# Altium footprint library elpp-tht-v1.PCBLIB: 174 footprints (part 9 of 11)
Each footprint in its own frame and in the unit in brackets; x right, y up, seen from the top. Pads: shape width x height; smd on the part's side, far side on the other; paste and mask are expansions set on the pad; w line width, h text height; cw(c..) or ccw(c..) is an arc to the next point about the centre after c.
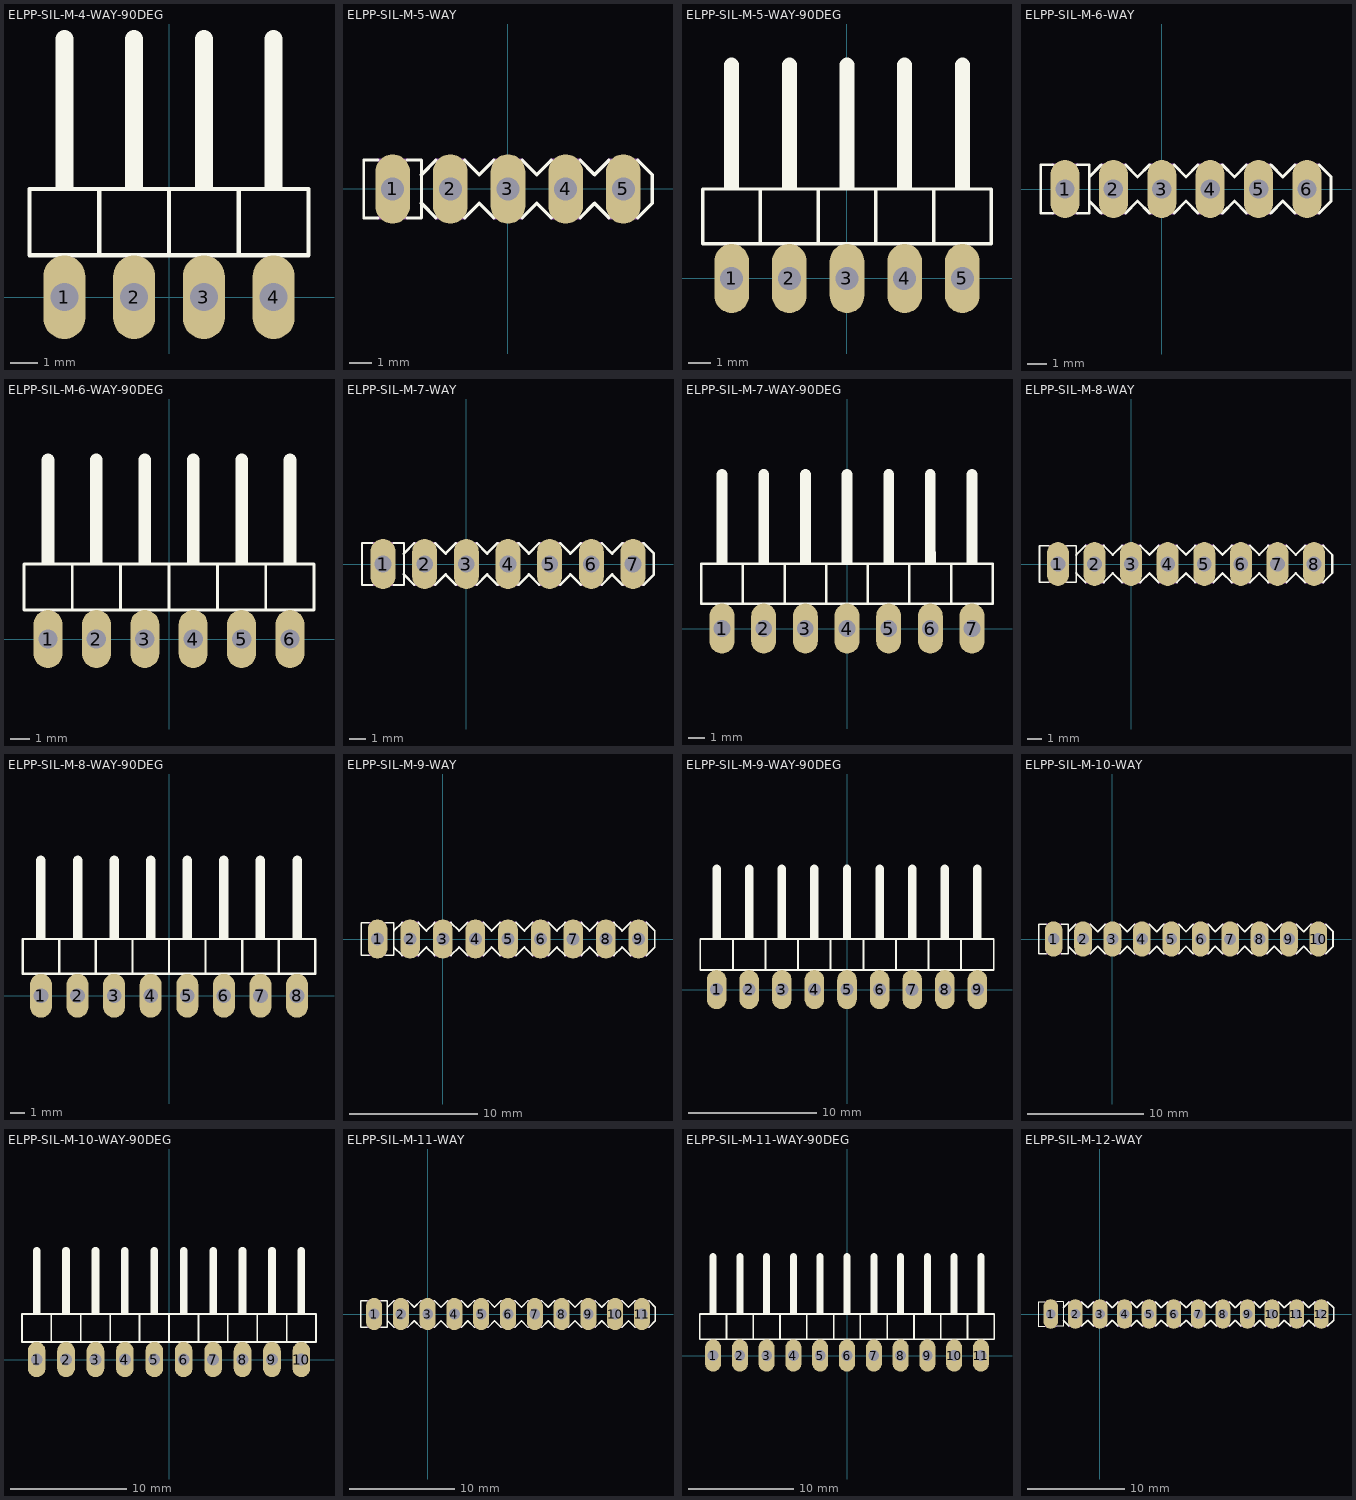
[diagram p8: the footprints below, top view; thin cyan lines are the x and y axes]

## ELPP-SIL-M-4-WAY-90DEG [mil]
pads (4):
  oval 60x120 hole 40: 1(-150,0) 2(-50,0) 3(50,0) 4(150,0)
Top Overlay:
  rectangle: -163,155 -137,185
  rectangle: -63,155 -37,185
  rectangle: 37,155 63,185
  rectangle: 137,155 163,185
  lines w6: -100,60 -100,155 ; -100,60 -200,60 -200,155 -100,155 ; -100,60 0,60 ; -100,155 0,155 ; 0,60 100,60 ; 0,60 0,155 ; 0,155 100,155 ; 100,60 200,60 200,155 100,155 ; 100,60 100,155
  lines w26: -150,185 -150,370 ; -50,185 -50,370 ; 50,185 50,370 ; 150,185 150,370
Mechanical 2:
  text ">NAME" at -210,140 h42.5
Mechanical 4:
  text ">VALUE" at 220,95 h42.5
Mechanical 16:
  rectangle: 137,34 163,60
  rectangle: 37,34 63,60
  rectangle: 137,-13 163,34
  rectangle: 37,-13 63,34
  rectangle: -63,34 -37,60
  rectangle: -163,34 -137,60
  rectangle: -63,-13 -37,34
  rectangle: -163,-13 -137,34
  text "1" at -125,95 h77.5
  text "2" at -25,95 h77.5
  text "3" at 75,95 h77.5
  text "4" at 175,95 h77.5

## ELPP-SIL-M-5-WAY [mil]
pads (5):
  oval 60x120 hole 40: 1(-200,0) 2(-100,0) 3(0,0) 4(100,0) 5(200,0)
Top Overlay:
  lines w5: -225,-50 -250,-50 -250,50 -225,50 ; -175,-50 -150,-50 -150,50 -175,50
  lines w6: -150,-25 -125,-50 ; -150,25 -125,50 ; -75,-50 -50,-25 -25,-50 ; -75,50 -50,25 -25,50 ; 25,-50 50,-25 75,-50 ; 25,50 50,25 75,50 ; 125,-50 150,-25 175,-50 ; 125,50 150,25 175,50 ; 225,-50 250,-25 250,25 225,50
Mechanical 2:
  text ">NAME" at -250,75 h42.5
Mechanical 4:
  text ">VALUE" at -250,-125 h42.5
Mechanical 16:
  rectangle: -110,-10 -90,10
  rectangle: -210,-10 -190,10
  rectangle: -10,-10 10,10
  rectangle: 190,-10 210,10
  rectangle: 90,-10 110,10
  lines w5: -225,-50 -175,-50 ; -225,50 -175,50
  lines w6: -125,-50 -75,-50 ; -125,50 -75,50 ; -25,-50 25,-50 ; -25,50 25,50 ; 75,-50 125,-50 ; 75,50 125,50 ; 175,-50 225,-50 ; 175,50 225,50

## ELPP-SIL-M-5-WAY-90DEG [mil]
pads (5):
  oval 60x120 hole 40: 1(-200,0) 2(-100,0) 3(0,0) 4(100,0) 5(200,0)
Top Overlay:
  rectangle: -213,155 -187,185
  rectangle: -113,155 -87,185
  rectangle: -13,155 13,185
  rectangle: 87,155 113,185
  rectangle: 187,155 213,185
  lines w6: -150,60 -150,155 ; -150,60 -250,60 -250,155 -150,155 ; -150,60 -50,60 ; -150,155 -50,155 ; -50,60 50,60 ; -50,60 -50,155 ; -50,155 50,155 ; 50,60 150,60 ; 50,60 50,155 ; 50,155 150,155 ; 150,60 250,60 250,155 150,155 ; 150,60 150,155
  lines w26: -200,185 -200,370 ; -100,185 -100,370 ; 0,185 0,370 ; 100,185 100,370 ; 200,185 200,370
Mechanical 2:
  text ">NAME" at -260,140 h42.5
Mechanical 4:
  text ">VALUE" at 270,95 h42.5
Mechanical 16:
  rectangle: 187,34 213,60
  rectangle: 87,34 113,60
  rectangle: -13,34 13,60
  rectangle: 187,-13 213,34
  rectangle: 87,-13 113,34
  rectangle: -13,-13 13,34
  rectangle: -113,34 -87,60
  rectangle: -213,34 -187,60
  rectangle: -113,-13 -87,34
  rectangle: -213,-13 -187,34
  text "1" at -175,95 h77.5
  text "2" at -75,95 h77.5
  text "3" at 25,95 h77.5
  text "4" at 125,95 h77.5
  text "5" at 225,95 h77.5

## ELPP-SIL-M-6-WAY [mil]
pads (6):
  oval 60x120 hole 40: 1(-200,0) 2(-100,0) 3(0,0) 4(100,0) 5(200,0) 6(300,0)
Top Overlay:
  lines w5: -225,-50 -250,-50 -250,50 -225,50 ; -175,-50 -150,-50 -150,50 -175,50
  lines w6: -150,-25 -125,-50 ; -150,25 -125,50 ; -75,-50 -50,-25 -25,-50 ; -75,50 -50,25 -25,50 ; 25,-50 50,-25 75,-50 ; 25,50 50,25 75,50 ; 125,-50 150,-25 175,-50 ; 125,50 150,25 175,50 ; 225,-50 250,-25 275,-50 ; 225,50 250,25 275,50 ; 325,-50 350,-25 350,25 325,50
Mechanical 2:
  text ">NAME" at -250,75 h42.5
Mechanical 4:
  text ">VALUE" at -250,-125 h42.5
Mechanical 16:
  rectangle: -110,-10 -90,10
  rectangle: -210,-10 -190,10
  rectangle: -10,-10 10,10
  rectangle: 190,-10 210,10
  rectangle: 90,-10 110,10
  rectangle: 290,-10 310,10
  lines w5: -225,-50 -175,-50 ; -225,50 -175,50
  lines w6: -125,-50 -75,-50 ; -125,50 -75,50 ; -25,-50 25,-50 ; -25,50 25,50 ; 75,-50 125,-50 ; 75,50 125,50 ; 175,-50 225,-50 ; 175,50 225,50 ; 275,-50 325,-50 ; 275,50 325,50

## ELPP-SIL-M-6-WAY-90DEG [mil]
pads (6):
  oval 60x120 hole 40: 1(-250,0) 2(-150,0) 3(-50,0) 4(50,0) 5(150,0) 6(250,0)
Top Overlay:
  rectangle: 237,155 263,185
  rectangle: -263,155 -237,185
  rectangle: -163,155 -137,185
  rectangle: -63,155 -37,185
  rectangle: 37,155 63,185
  rectangle: 137,155 163,185
  lines w6: -200,60 -200,155 ; -200,60 -300,60 -300,155 -200,155 ; -200,60 -100,60 ; -200,155 -100,155 ; -100,60 0,60 ; -100,60 -100,155 ; -100,155 0,155 ; 0,60 100,60 ; 0,60 0,155 ; 0,155 100,155 ; 100,60 200,60 ; 100,60 100,155 ; 100,155 200,155 ; 200,60 300,60 300,155 200,155 ; 200,60 200,155
  lines w26: -250,185 -250,370 ; -150,185 -150,370 ; -50,185 -50,370 ; 50,185 50,370 ; 150,185 150,370 ; 250,185 250,370
Mechanical 2:
  text ">NAME" at -310,140 h42.5
Mechanical 4:
  text ">VALUE" at 320,95 h42.5
Mechanical 16:
  rectangle: 237,34 263,60
  rectangle: 237,-13 263,34
  rectangle: 137,34 163,60
  rectangle: 37,34 63,60
  rectangle: -63,34 -37,60
  rectangle: 137,-13 163,34
  rectangle: 37,-13 63,34
  rectangle: -63,-13 -37,34
  rectangle: -163,34 -137,60
  rectangle: -263,34 -237,60
  rectangle: -163,-13 -137,34
  rectangle: -263,-13 -237,34
  text "1" at -225,95 h77.5
  text "2" at -125,95 h77.5
  text "3" at -25,95 h77.5
  text "4" at 75,95 h77.5
  text "5" at 175,95 h77.5
  text "6" at 275,95 h77.5

## ELPP-SIL-M-7-WAY [mil]
pads (7):
  oval 60x120 hole 40: 1(-200,0) 2(-100,0) 3(0,0) 4(100,0) 5(200,0) 6(300,0) 7(400,0)
Top Overlay:
  lines w5: -225,-50 -250,-50 -250,50 -225,50 ; -175,-50 -150,-50 -150,50 -175,50
  lines w6: -150,-25 -125,-50 ; -150,25 -125,50 ; -75,-50 -50,-25 -25,-50 ; -75,50 -50,25 -25,50 ; 25,-50 50,-25 75,-50 ; 25,50 50,25 75,50 ; 125,-50 150,-25 175,-50 ; 125,50 150,25 175,50 ; 225,-50 250,-25 275,-50 ; 225,50 250,25 275,50 ; 325,-50 350,-25 375,-50 ; 325,50 350,25 375,50 ; 425,-50 450,-25 450,25 425,50
Mechanical 2:
  text ">NAME" at -250,75 h42.5
Mechanical 4:
  text ">VALUE" at -250,-125 h42.5
Mechanical 16:
  rectangle: -110,-10 -90,10
  rectangle: -210,-10 -190,10
  rectangle: -10,-10 10,10
  rectangle: 190,-10 210,10
  rectangle: 90,-10 110,10
  rectangle: 290,-10 310,10
  rectangle: 390,-10 410,10
  lines w5: -225,-50 -175,-50 ; -225,50 -175,50
  lines w6: -125,-50 -75,-50 ; -125,50 -75,50 ; -25,-50 25,-50 ; -25,50 25,50 ; 75,-50 125,-50 ; 75,50 125,50 ; 175,-50 225,-50 ; 175,50 225,50 ; 275,-50 325,-50 ; 275,50 325,50 ; 375,-50 425,-50 ; 375,50 425,50

## ELPP-SIL-M-7-WAY-90DEG [mil]
pads (7):
  oval 60x120 hole 40: 1(-300,0) 2(-200,0) 3(-100,0) 4(0,0) 5(100,0) 6(200,0) 7(300,0)
Top Overlay:
  rectangle: 187,155 213,185
  rectangle: 287,155 313,185
  rectangle: -313,155 -287,185
  rectangle: -213,155 -187,185
  rectangle: -113,155 -87,185
  rectangle: -13,155 13,185
  rectangle: 87,155 113,185
  lines w6: -250,60 -250,155 ; -250,60 -350,60 -350,155 -250,155 ; -250,60 -150,60 ; -250,155 -150,155 ; -150,60 -50,60 ; -150,60 -150,155 ; -150,155 -50,155 ; -50,60 50,60 ; -50,60 -50,155 ; -50,155 50,155 ; 50,60 150,60 ; 50,60 50,155 ; 50,155 150,155 ; 150,60 250,60 ; 150,60 150,155 ; 150,155 250,155 ; 250,60 250,155 ; 250,60 350,60 350,155 250,155
  lines w26: -300,185 -300,370 ; -200,185 -200,370 ; -100,185 -100,370 ; 0,185 0,370 ; 100,185 100,370 ; 200,185 200,370 ; 300,185 300,370
Mechanical 2:
  text ">NAME" at -360,140 h42.5
Mechanical 4:
  text ">VALUE" at 370,95 h42.5
Mechanical 16:
  rectangle: 287,34 313,60
  rectangle: 287,-13 313,34
  rectangle: 187,34 213,60
  rectangle: 187,-13 213,34
  rectangle: 87,34 113,60
  rectangle: -13,34 13,60
  rectangle: -113,34 -87,60
  rectangle: 87,-13 113,34
  rectangle: -13,-13 13,34
  rectangle: -113,-13 -87,34
  rectangle: -213,34 -187,60
  rectangle: -313,34 -287,60
  rectangle: -213,-13 -187,34
  rectangle: -313,-13 -287,34
  text "1" at -275,95 h77.5
  text "2" at -175,95 h77.5
  text "3" at -75,95 h77.5
  text "4" at 25,95 h77.5
  text "5" at 125,95 h77.5
  text "6" at 225,95 h77.5
  text "7" at 325,95 h77.5

## ELPP-SIL-M-8-WAY [mil]
pads (8):
  oval 60x120 hole 40: 1(-200,0) 2(-100,0) 3(0,0) 4(100,0) 5(200,0) 6(300,0) 7(400,0) 8(500,0)
Top Overlay:
  lines w5: -225,-50 -250,-50 -250,50 -225,50 ; -175,-50 -150,-50 -150,50 -175,50
  lines w6: -150,-25 -125,-50 ; -150,25 -125,50 ; -75,-50 -50,-25 -25,-50 ; -75,50 -50,25 -25,50 ; 25,-50 50,-25 75,-50 ; 25,50 50,25 75,50 ; 125,-50 150,-25 175,-50 ; 125,50 150,25 175,50 ; 225,-50 250,-25 275,-50 ; 225,50 250,25 275,50 ; 325,-50 350,-25 375,-50 ; 325,50 350,25 375,50 ; 425,-50 450,-25 475,-50 ; 425,50 450,25 475,50 ; 525,-50 550,-25 550,25 525,50
Mechanical 2:
  text ">NAME" at -250,75 h42.5
Mechanical 4:
  text ">VALUE" at -250,-125 h42.5
Mechanical 16:
  rectangle: -110,-10 -90,10
  rectangle: -210,-10 -190,10
  rectangle: -10,-10 10,10
  rectangle: 190,-10 210,10
  rectangle: 90,-10 110,10
  rectangle: 290,-10 310,10
  rectangle: 390,-10 410,10
  rectangle: 490,-10 510,10
  lines w5: -225,-50 -175,-50 ; -225,50 -175,50
  lines w6: -125,-50 -75,-50 ; -125,50 -75,50 ; -25,-50 25,-50 ; -25,50 25,50 ; 75,-50 125,-50 ; 75,50 125,50 ; 175,-50 225,-50 ; 175,50 225,50 ; 275,-50 325,-50 ; 275,50 325,50 ; 375,-50 425,-50 ; 375,50 425,50 ; 475,-50 525,-50 ; 475,50 525,50

## ELPP-SIL-M-8-WAY-90DEG [mil]
pads (8):
  oval 60x120 hole 40: 1(-350,0) 2(-250,0) 3(-150,0) 4(-50,0) 5(50,0) 6(150,0) 7(250,0) 8(350,0)
Top Overlay:
  rectangle: 137,155 163,185
  rectangle: 237,155 263,185
  rectangle: 337,155 363,185
  rectangle: -363,155 -337,185
  rectangle: -263,155 -237,185
  rectangle: -163,155 -137,185
  rectangle: -63,155 -37,185
  rectangle: 37,155 63,185
  lines w6: -300,60 -300,155 ; -300,60 -400,60 -400,155 -300,155 ; -300,60 -200,60 ; -300,155 -200,155 ; -200,60 -100,60 ; -200,60 -200,155 ; -200,155 -100,155 ; -100,60 0,60 ; -100,60 -100,155 ; -100,155 0,155 ; 0,60 100,60 ; 0,60 0,155 ; 0,155 100,155 ; 100,60 200,60 ; 100,60 100,155 ; 100,155 200,155 ; 200,60 200,155 ; 200,60 300,60 ; 200,155 300,155 ; 300,60 400,60 400,155 300,155 ; 300,60 300,155
  lines w26: -350,185 -350,370 ; -250,185 -250,370 ; -150,185 -150,370 ; -50,185 -50,370 ; 50,185 50,370 ; 150,185 150,370 ; 250,185 250,370 ; 350,185 350,370
Mechanical 2:
  text ">NAME" at -410,140 h42.5
Mechanical 4:
  text ">VALUE" at 420,95 h42.5
Mechanical 16:
  rectangle: 337,34 363,60
  rectangle: 337,-13 363,34
  rectangle: 237,34 263,60
  rectangle: 237,-13 263,34
  rectangle: 137,34 163,60
  rectangle: 137,-13 163,34
  rectangle: 37,34 63,60
  rectangle: -63,34 -37,60
  rectangle: -163,34 -137,60
  rectangle: 37,-13 63,34
  rectangle: -63,-13 -37,34
  rectangle: -163,-13 -137,34
  rectangle: -263,34 -237,60
  rectangle: -363,34 -337,60
  rectangle: -263,-13 -237,34
  rectangle: -363,-13 -337,34
  text "1" at -325,95 h77.5
  text "2" at -225,95 h77.5
  text "3" at -125,95 h77.5
  text "4" at -25,95 h77.5
  text "5" at 75,95 h77.5
  text "6" at 175,95 h77.5
  text "7" at 275,95 h77.5
  text "8" at 375,95 h77.5

## ELPP-SIL-M-9-WAY [mil]
pads (9):
  oval 60x120 hole 40: 1(-200,0) 2(-100,0) 3(0,0) 4(100,0) 5(200,0) 6(300,0) 7(400,0) 8(500,0) 9(600,0)
Top Overlay:
  lines w5: -225,-50 -250,-50 -250,50 -225,50 ; -175,-50 -150,-50 -150,50 -175,50
  lines w6: -150,-25 -125,-50 ; -150,25 -125,50 ; -75,-50 -50,-25 -25,-50 ; -75,50 -50,25 -25,50 ; 25,-50 50,-25 75,-50 ; 25,50 50,25 75,50 ; 125,-50 150,-25 175,-50 ; 125,50 150,25 175,50 ; 225,-50 250,-25 275,-50 ; 225,50 250,25 275,50 ; 325,-50 350,-25 375,-50 ; 325,50 350,25 375,50 ; 425,-50 450,-25 475,-50 ; 425,50 450,25 475,50 ; 525,-50 550,-25 575,-50 ; 525,50 550,25 575,50 ; 625,-50 650,-25 650,25 625,50
Mechanical 2:
  text ">NAME" at -250,75 h42.5
Mechanical 4:
  text ">VALUE" at -250,-125 h42.5
Mechanical 16:
  rectangle: -110,-10 -90,10
  rectangle: -210,-10 -190,10
  rectangle: -10,-10 10,10
  rectangle: 190,-10 210,10
  rectangle: 90,-10 110,10
  rectangle: 290,-10 310,10
  rectangle: 390,-10 410,10
  rectangle: 490,-10 510,10
  rectangle: 590,-10 610,10
  lines w5: -225,-50 -175,-50 ; -225,50 -175,50
  lines w6: -125,-50 -75,-50 ; -125,50 -75,50 ; -25,-50 25,-50 ; -25,50 25,50 ; 75,-50 125,-50 ; 75,50 125,50 ; 175,-50 225,-50 ; 175,50 225,50 ; 275,-50 325,-50 ; 275,50 325,50 ; 375,-50 425,-50 ; 375,50 425,50 ; 475,-50 525,-50 ; 475,50 525,50 ; 575,-50 625,-50 ; 575,50 625,50

## ELPP-SIL-M-9-WAY-90DEG [mil]
pads (9):
  oval 60x120 hole 40: 1(-400,0) 2(-300,0) 3(-200,0) 4(-100,0) 5(0,0) 6(100,0) 7(200,0) 8(300,0) 9(400,0)
Top Overlay:
  rectangle: 87,155 113,185
  rectangle: 187,155 213,185
  rectangle: 287,155 313,185
  rectangle: 387,155 413,185
  rectangle: -413,155 -387,185
  rectangle: -313,155 -287,185
  rectangle: -213,155 -187,185
  rectangle: -113,155 -87,185
  rectangle: -13,155 13,185
  lines w6: -350,60 -350,155 ; -350,60 -450,60 -450,155 -350,155 ; -350,60 -250,60 ; -350,155 -250,155 ; -250,60 -150,60 ; -250,60 -250,155 ; -250,155 -150,155 ; -150,60 -50,60 ; -150,60 -150,155 ; -150,155 -50,155 ; -50,60 50,60 ; -50,60 -50,155 ; -50,155 50,155 ; 50,60 150,60 ; 50,60 50,155 ; 50,155 150,155 ; 150,60 150,155 ; 150,60 250,60 ; 150,155 250,155 ; 250,60 350,60 ; 250,60 250,155 ; 250,155 350,155 ; 350,60 450,60 450,155 350,155 ; 350,60 350,155
  lines w26: -400,185 -400,370 ; -300,185 -300,370 ; -200,185 -200,370 ; -100,185 -100,370 ; 0,185 0,370 ; 100,185 100,370 ; 200,185 200,370 ; 300,185 300,370 ; 400,185 400,370
Mechanical 2:
  text ">NAME" at -460,140 h42.5
Mechanical 4:
  text ">VALUE" at 470,95 h42.5
Mechanical 16:
  rectangle: 387,34 413,60
  rectangle: 287,34 313,60
  rectangle: 387,-13 413,34
  rectangle: 287,-13 313,34
  rectangle: 187,34 213,60
  rectangle: 187,-13 213,34
  rectangle: 87,34 113,60
  rectangle: 87,-13 113,34
  rectangle: -13,34 13,60
  rectangle: -113,34 -87,60
  rectangle: -213,34 -187,60
  rectangle: -13,-13 13,34
  rectangle: -113,-13 -87,34
  rectangle: -213,-13 -187,34
  rectangle: -313,34 -287,60
  rectangle: -413,34 -387,60
  rectangle: -313,-13 -287,34
  rectangle: -413,-13 -387,34
  text "1" at -375,95 h77.5
  text "2" at -275,95 h77.5
  text "3" at -175,95 h77.5
  text "4" at -75,95 h77.5
  text "5" at 25,95 h77.5
  text "6" at 125,95 h77.5
  text "7" at 225,95 h77.5
  text "8" at 325,95 h77.5
  text "9" at 425,95 h77.5

## ELPP-SIL-M-10-WAY [mil]
pads (10):
  oval 60x120 hole 40: 1(-200,0) 2(-100,0) 3(0,0) 4(100,0) 5(200,0) 6(300,0) 7(400,0) 8(500,0) 9(600,0) 10(700,0)
Top Overlay:
  lines w5: -225,-50 -250,-50 -250,50 -225,50 ; -175,-50 -150,-50 -150,50 -175,50
  lines w6: -150,-25 -125,-50 ; -150,25 -125,50 ; -75,-50 -50,-25 -25,-50 ; -75,50 -50,25 -25,50 ; 25,-50 50,-25 75,-50 ; 25,50 50,25 75,50 ; 125,-50 150,-25 175,-50 ; 125,50 150,25 175,50 ; 225,-50 250,-25 275,-50 ; 225,50 250,25 275,50 ; 325,-50 350,-25 375,-50 ; 325,50 350,25 375,50 ; 425,-50 450,-25 475,-50 ; 425,50 450,25 475,50 ; 525,-50 550,-25 575,-50 ; 525,50 550,25 575,50 ; 625,-50 650,-25 675,-50 ; 625,50 650,25 675,50 ; 725,-50 750,-25 750,25 725,50
Mechanical 2:
  text ">NAME" at -250,75 h42.5
Mechanical 4:
  text ">VALUE" at -250,-125 h42.5
Mechanical 16:
  rectangle: -110,-10 -90,10
  rectangle: -210,-10 -190,10
  rectangle: -10,-10 10,10
  rectangle: 190,-10 210,10
  rectangle: 90,-10 110,10
  rectangle: 290,-10 310,10
  rectangle: 390,-10 410,10
  rectangle: 490,-10 510,10
  rectangle: 590,-10 610,10
  rectangle: 690,-10 710,10
  lines w5: -225,-50 -175,-50 ; -225,50 -175,50
  lines w6: -125,-50 -75,-50 ; -125,50 -75,50 ; -25,-50 25,-50 ; -25,50 25,50 ; 75,-50 125,-50 ; 75,50 125,50 ; 175,-50 225,-50 ; 175,50 225,50 ; 275,-50 325,-50 ; 275,50 325,50 ; 375,-50 425,-50 ; 375,50 425,50 ; 475,-50 525,-50 ; 475,50 525,50 ; 575,-50 625,-50 ; 575,50 625,50 ; 675,-50 725,-50 ; 675,50 725,50

## ELPP-SIL-M-10-WAY-90DEG [mil]
pads (10):
  oval 60x120 hole 40: 1(-450,0) 2(-350,0) 3(-250,0) 4(-150,0) 5(-50,0) 6(50,0) 7(150,0) 8(250,0) 9(350,0) 10(450,0)
Top Overlay:
  rectangle: 37,155 63,185
  rectangle: 137,155 163,185
  rectangle: 237,155 263,185
  rectangle: 337,155 363,185
  rectangle: 437,155 463,185
  rectangle: -463,155 -437,185
  rectangle: -363,155 -337,185
  rectangle: -263,155 -237,185
  rectangle: -163,155 -137,185
  rectangle: -63,155 -37,185
  lines w6: -400,60 -400,155 ; -400,60 -500,60 -500,155 -400,155 ; -400,60 -300,60 ; -400,155 -300,155 ; -300,60 -200,60 ; -300,60 -300,155 ; -300,155 -200,155 ; -200,60 -100,60 ; -200,60 -200,155 ; -200,155 -100,155 ; -100,60 0,60 ; -100,60 -100,155 ; -100,155 0,155 ; 0,60 100,60 ; 0,60 0,155 ; 0,155 100,155 ; 100,60 100,155 ; 100,60 200,60 ; 100,155 200,155 ; 200,60 300,60 ; 200,60 200,155 ; 200,155 300,155 ; 300,60 400,60 ; 300,60 300,155 ; 300,155 400,155 ; 400,60 500,60 500,155 400,155 ; 400,60 400,155
  lines w26: -450,185 -450,370 ; -350,185 -350,370 ; -250,185 -250,370 ; -150,185 -150,370 ; -50,185 -50,370 ; 50,185 50,370 ; 150,185 150,370 ; 250,185 250,370 ; 350,185 350,370 ; 450,185 450,370
Mechanical 2:
  text ">NAME" at -510,140 h42.5
Mechanical 4:
  text ">VALUE" at 520,95 h42.5
Mechanical 16:
  rectangle: 437,34 463,60
  rectangle: 437,-13 463,34
  rectangle: 337,34 363,60
  rectangle: 237,34 263,60
  rectangle: 337,-13 363,34
  rectangle: 237,-13 263,34
  rectangle: 137,34 163,60
  rectangle: 137,-13 163,34
  rectangle: 37,34 63,60
  rectangle: 37,-13 63,34
  rectangle: -63,34 -37,60
  rectangle: -163,34 -137,60
  rectangle: -263,34 -237,60
  rectangle: -63,-13 -37,34
  rectangle: -163,-13 -137,34
  rectangle: -263,-13 -237,34
  rectangle: -363,34 -337,60
  rectangle: -463,34 -437,60
  rectangle: -363,-13 -337,34
  rectangle: -463,-13 -437,34
  text "1" at -425,95 h77.5
  text "2" at -325,95 h77.5
  text "3" at -225,95 h77.5
  text "4" at -125,95 h77.5
  text "5" at -25,95 h77.5
  text "6" at 75,95 h77.5
  text "7" at 175,95 h77.5
  text "8" at 275,95 h77.5
  text "9" at 375,95 h77.5
  text "10" at 475,75 h77.5

## ELPP-SIL-M-11-WAY [mil]
pads (11):
  oval 60x120 hole 40: 1(-200,0) 2(-100,0) 3(0,0) 4(100,0) 5(200,0) 6(300,0) 7(400,0) 8(500,0) 9(600,0) 10(700,0) 11(800,0)
Top Overlay:
  lines w5: -225,-50 -250,-50 -250,50 -225,50 ; -175,-50 -150,-50 -150,50 -175,50
  lines w6: -150,-25 -125,-50 ; -150,25 -125,50 ; -75,-50 -50,-25 -25,-50 ; -75,50 -50,25 -25,50 ; 25,-50 50,-25 75,-50 ; 25,50 50,25 75,50 ; 125,-50 150,-25 175,-50 ; 125,50 150,25 175,50 ; 225,-50 250,-25 275,-50 ; 225,50 250,25 275,50 ; 325,-50 350,-25 375,-50 ; 325,50 350,25 375,50 ; 425,-50 450,-25 475,-50 ; 425,50 450,25 475,50 ; 525,-50 550,-25 575,-50 ; 525,50 550,25 575,50 ; 625,-50 650,-25 675,-50 ; 625,50 650,25 675,50 ; 725,-50 750,-25 775,-50 ; 725,50 750,25 775,50 ; 825,-50 850,-25 850,25 825,50
Mechanical 2:
  text ">NAME" at -250,75 h42.5
Mechanical 4:
  text ">VALUE" at -250,-125 h42.5
Mechanical 16:
  rectangle: -110,-10 -90,10
  rectangle: -210,-10 -190,10
  rectangle: -10,-10 10,10
  rectangle: 190,-10 210,10
  rectangle: 90,-10 110,10
  rectangle: 290,-10 310,10
  rectangle: 390,-10 410,10
  rectangle: 490,-10 510,10
  rectangle: 590,-10 610,10
  rectangle: 690,-10 710,10
  rectangle: 790,-10 810,10
  lines w5: -225,-50 -175,-50 ; -225,50 -175,50
  lines w6: -125,-50 -75,-50 ; -125,50 -75,50 ; -25,-50 25,-50 ; -25,50 25,50 ; 75,-50 125,-50 ; 75,50 125,50 ; 175,-50 225,-50 ; 175,50 225,50 ; 275,-50 325,-50 ; 275,50 325,50 ; 375,-50 425,-50 ; 375,50 425,50 ; 475,-50 525,-50 ; 475,50 525,50 ; 575,-50 625,-50 ; 575,50 625,50 ; 675,-50 725,-50 ; 675,50 725,50 ; 775,-50 825,-50 ; 775,50 825,50

## ELPP-SIL-M-11-WAY-90DEG [mil]
pads (11):
  oval 60x120 hole 40: 1(-500,0) 2(-400,0) 3(-300,0) 4(-200,0) 5(-100,0) 6(0,0) 7(100,0) 8(200,0) 9(300,0) 10(400,0) 11(500,0)
Top Overlay:
  rectangle: 487,155 513,185
  rectangle: -13,155 13,185
  rectangle: 87,155 113,185
  rectangle: 187,155 213,185
  rectangle: 287,155 313,185
  rectangle: 387,155 413,185
  rectangle: -513,155 -487,185
  rectangle: -413,155 -387,185
  rectangle: -313,155 -287,185
  rectangle: -213,155 -187,185
  rectangle: -113,155 -87,185
  lines w6: -450,60 -450,155 ; -450,60 -550,60 -550,155 -450,155 ; -450,60 -350,60 ; -450,155 -350,155 ; -350,60 -250,60 ; -350,60 -350,155 ; -350,155 -250,155 ; -250,60 -150,60 ; -250,60 -250,155 ; -250,155 -150,155 ; -150,60 -50,60 ; -150,60 -150,155 ; -150,155 -50,155 ; -50,60 50,60 ; -50,60 -50,155 ; -50,155 50,155 ; 50,60 50,155 ; 50,60 150,60 ; 50,155 150,155 ; 150,60 250,60 ; 150,60 150,155 ; 150,155 250,155 ; 250,60 350,60 ; 250,60 250,155 ; 250,155 350,155 ; 350,60 450,60 ; 350,60 350,155 ; 350,155 450,155 ; 450,60 550,60 550,155 450,155 ; 450,60 450,155
  lines w26: -500,185 -500,370 ; -400,185 -400,370 ; -300,185 -300,370 ; -200,185 -200,370 ; -100,185 -100,370 ; 0,185 0,370 ; 100,185 100,370 ; 200,185 200,370 ; 300,185 300,370 ; 400,185 400,370 ; 500,185 500,370
Mechanical 2:
  text ">NAME" at -560,140 h42.5
Mechanical 4:
  text ">VALUE" at 570,95 h42.5
Mechanical 16:
  rectangle: 487,34 513,60
  rectangle: 387,34 413,60
  rectangle: 487,-13 513,34
  rectangle: 387,-13 413,34
  rectangle: 287,34 313,60
  rectangle: 187,34 213,60
  rectangle: 287,-13 313,34
  rectangle: 187,-13 213,34
  rectangle: 87,34 113,60
  rectangle: 87,-13 113,34
  rectangle: -13,34 13,60
  rectangle: -13,-13 13,34
  rectangle: -113,34 -87,60
  rectangle: -213,34 -187,60
  rectangle: -313,34 -287,60
  rectangle: -113,-13 -87,34
  rectangle: -213,-13 -187,34
  rectangle: -313,-13 -287,34
  rectangle: -413,34 -387,60
  rectangle: -513,34 -487,60
  rectangle: -413,-13 -387,34
  rectangle: -513,-13 -487,34
  text "1" at -475,95 h77.5
  text "2" at -375,95 h77.5
  text "3" at -275,95 h77.5
  text "4" at -175,95 h77.5
  text "5" at -75,95 h77.5
  text "6" at 25,95 h77.5
  text "7" at 125,95 h77.5
  text "8" at 225,95 h77.5
  text "9" at 325,95 h77.5
  text "10" at 425,75 h77.5
  text "11" at 525,75 h77.5

## ELPP-SIL-M-12-WAY [mil]
pads (12):
  oval 60x120 hole 40: 1(-200,0) 2(-100,0) 3(0,0) 4(100,0) 5(200,0) 6(300,0) 7(400,0) 8(500,0) 9(600,0) 10(700,0) 11(800,0) 12(900,0)
Top Overlay:
  lines w5: -225,-50 -250,-50 -250,50 -225,50 ; -175,-50 -150,-50 -150,50 -175,50
  lines w6: -150,-25 -125,-50 ; -150,25 -125,50 ; -75,-50 -50,-25 -25,-50 ; -75,50 -50,25 -25,50 ; 25,-50 50,-25 75,-50 ; 25,50 50,25 75,50 ; 125,-50 150,-25 175,-50 ; 125,50 150,25 175,50 ; 225,-50 250,-25 275,-50 ; 225,50 250,25 275,50 ; 325,-50 350,-25 375,-50 ; 325,50 350,25 375,50 ; 425,-50 450,-25 475,-50 ; 425,50 450,25 475,50 ; 525,-50 550,-25 575,-50 ; 525,50 550,25 575,50 ; 625,-50 650,-25 675,-50 ; 625,50 650,25 675,50 ; 725,-50 750,-25 775,-50 ; 725,50 750,25 775,50 ; 825,-50 850,-25 875,-50 ; 825,50 850,25 875,50 ; 925,-50 950,-25 950,25 925,50
Mechanical 2:
  text ">NAME" at -250,75 h42.5
Mechanical 4:
  text ">VALUE" at -250,-125 h42.5
Mechanical 16:
  rectangle: -110,-10 -90,10
  rectangle: -210,-10 -190,10
  rectangle: -10,-10 10,10
  rectangle: 190,-10 210,10
  rectangle: 90,-10 110,10
  rectangle: 290,-10 310,10
  rectangle: 390,-10 410,10
  rectangle: 490,-10 510,10
  rectangle: 590,-10 610,10
  rectangle: 690,-10 710,10
  rectangle: 790,-10 810,10
  rectangle: 890,-10 910,10
  lines w5: -225,-50 -175,-50 ; -225,50 -175,50
  lines w6: -125,-50 -75,-50 ; -125,50 -75,50 ; -25,-50 25,-50 ; -25,50 25,50 ; 75,-50 125,-50 ; 75,50 125,50 ; 175,-50 225,-50 ; 175,50 225,50 ; 275,-50 325,-50 ; 275,50 325,50 ; 375,-50 425,-50 ; 375,50 425,50 ; 475,-50 525,-50 ; 475,50 525,50 ; 575,-50 625,-50 ; 575,50 625,50 ; 675,-50 725,-50 ; 675,50 725,50 ; 775,-50 825,-50 ; 775,50 825,50 ; 875,-50 925,-50 ; 875,50 925,50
